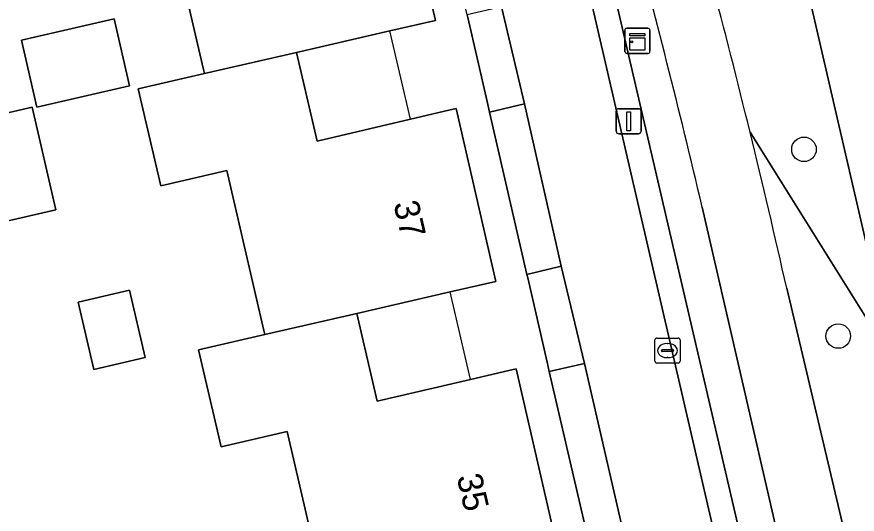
# Model space of a CAD drawing. Extents: x 156412 to 157779, y 382335 to 383768.
# Drawn here: x 156939.8 to 156973.27, y 382923.76 to 382943.57 of the extents above; entities that cross this region are included whole.
import ezdxf

# ---------------------------------------------------------------- set-up
doc = ezdxf.new("R2010")
doc.units = 0
for name, color, linetype in [('IMGEO_Berm_groen', 7, 'Continuous'), ('IMGEO_Boom', 7, 'Continuous'), ('IMGEO_Erf', 7, 'Continuous'), ('IMGEO_Fietspad_gesloten', 7, 'Continuous'), ('IMGEO_Groenvoorziening', 7, 'Continuous'), ('IMGEO_Haag', 7, 'Continuous'), ('IMGEO_Kast', 7, 'Continuous'), ('IMGEO_Kolk', 7, 'Continuous'), ('IMGEO_Lichtmast', 7, 'Continuous'), ('IMGEO_Pand', 7, 'Continuous'), ('IMGEO_Pand_nummerreeks', 7, 'Continuous'), ('IMGEO_Pand_overbouw', 7, 'Continuous'), ('IMGEO_Rijbaan_lokaal_open', 7, 'Continuous'), ('IMGEO_Rijbaan_regionaal_gesloten', 7, 'Continuous'), ('IMGEO_Voetpad_open', 7, 'Continuous')]:
    doc.layers.add(name, color=color, linetype=linetype)

msp = doc.modelspace()

# ---------------------------------------------------------------- linework, layer by layer
at = {"layer": 'IMGEO_Berm_groen'}
for points in [[(156969, 382938.98), (156974.712, 382929.839), (156971.043, 382945.704)], [(156980.671, 382903.778), (156977.118, 382919.414), (156974.712, 382929.839), (156969, 382938.98)], [(156970.46, 382932.76), (156978.859, 382897.233)]]:
    msp.add_lwpolyline(points, dxfattribs=at)
for points in [[(156960.013, 382940.109), (156958.628, 382939.774), (156960.116, 382933.313), (156961.48, 382933.643)], [(156962.404, 382929.759), (156961.007, 382929.446), (156962.495, 382922.988), (156963.893, 382923.301)]]:
    msp.add_lwpolyline(points, close=True, dxfattribs=at)
for centre, radius, start, end in [((156640.671, 382858.578), 338.03, 13.75987, 15.89102), ((156644.824, 382859.606), 333.752, 12.66129, 13.75813)]:
    msp.add_arc(centre, radius, start, end, dxfattribs=at)
at = {"layer": 'IMGEO_Boom'}
for centre in [(156971.148, 382938.294), (156972.514, 382930.857)]:
    msp.add_circle(centre, 0.489, dxfattribs=at)
at = {"layer": 'IMGEO_Erf'}
for points in [[(156943.885, 382953.85), (156941.48, 382953.262), (156933.668, 382951.485), (156923.153, 382949.089), (156923.606, 382947.103), (156935.097, 382949.756), (156936.197, 382944.981), (156936.242, 382944.786), (156932.327, 382943.884), (156933.568, 382938.516), (156933.595, 382938.399), (156940.416, 382939.971), (156941.36, 382935.888), (156934.538, 382934.316), (156935.969, 382928.126), (156938.368, 382917.746)], [(156955.398, 382948.066), (156956.474, 382943.428), (156954.652, 382943.009), (156950.939, 382942.155), (156951.763, 382938.625), (156955.473, 382939.492), (156957.002, 382939.85), (156957.294, 382939.918), (156958.877, 382933.032), (156957.056, 382932.613), (156953.343, 382931.76), (156954.156, 382928.261), (156957.867, 382929.123), (156959.396, 382929.479), (156959.688, 382929.547), (156961.304, 382922.502)], [(156952.114, 382920.354), (156950.566, 382927.05), (156947.935, 382926.443), (156947.041, 382930.311), (156949.673, 382930.916), (156949.634, 382931.083), (156949.303, 382932.514), (156948.164, 382937.446), (156945.533, 382936.839), (156944.639, 382940.707), (156947.27, 382941.312), (156947.231, 382941.479), (156946.995, 382942.502), (156945.95, 382947.023)], [(156962.495, 382922.988), (156961.007, 382929.446), (156960.923, 382929.812), (156960.147, 382933.18), (156960.116, 382933.313), (156958.628, 382939.774), (156958.531, 382940.198), (156957.757, 382943.551), (156957.734, 382943.651), (156957.201, 382945.894)]]:
    msp.add_lwpolyline(points, dxfattribs=at)
for points in [[(156939.981, 382942.644), (156943.671, 382943.497), (156944.288, 382940.825), (156940.598, 382939.972)], [(156942.24, 382932.206), (156944.293, 382932.681), (156944.913, 382929.996), (156942.861, 382929.522)]]:
    msp.add_lwpolyline(points, close=True, dxfattribs=at)
at = {"layer": 'IMGEO_Fietspad_gesloten'}
for points in [[(156967.094, 382935.993), (156971.591, 382916.445), (156974.262, 382905.075), (156976.72, 382895.4)], [(156978.859, 382897.233), (156970.46, 382932.76)]]:
    msp.add_lwpolyline(points, dxfattribs=at)
for centre, radius, start, end in [((156640.671, 382858.578), 338.03, 13.75987, 15.89102), ((156682.4, 382869.623), 292.328, 13.12282, 15.44279), ((156644.824, 382859.606), 333.752, 12.66129, 13.75813)]:
    msp.add_arc(centre, radius, start, end, dxfattribs=at)
at = {"layer": 'IMGEO_Groenvoorziening'}
msp.add_lwpolyline([(156962.016, 382947.078), (156969.739, 382913.653), (156970.724, 382913.858), (156963.505, 382944.87)], dxfattribs=at)
at = {"layer": 'IMGEO_Haag'}
msp.add_lwpolyline([(156962.016, 382947.078), (156969.739, 382913.653), (156970.724, 382913.858), (156963.505, 382944.87)], dxfattribs=at)
at = {"layer": 'IMGEO_Kast'}
for p, q in [((156964.013, 382942.192), (156964.013, 382943.033)), ((156964.013, 382943.033), (156964.013, 382942.192)), ((156964.088, 382943.117), (156964.929, 382943.117)), ((156964.929, 382943.117), (156964.088, 382943.117)), ((156965.013, 382943.042), (156965.013, 382942.201)), ((156965.013, 382942.201), (156965.013, 382943.042)), ((156964.938, 382942.117), (156964.097, 382942.117)), ((156964.097, 382942.117), (156964.938, 382942.117))]:
    msp.add_line(p, q, dxfattribs=at)
for points in [[(156964.208, 382942.907), (156964.808, 382942.907), (156964.808, 382942.822), (156964.208, 382942.822), (156964.208, 382942.907)], [(156964.208, 382942.732), (156964.808, 382942.732), (156964.808, 382942.243), (156964.208, 382942.243), (156964.208, 382942.732)]]:
    msp.add_lwpolyline(points, dxfattribs=at)
msp.add_circle((156964.292, 382942.581), 0.0377, dxfattribs=at)
for centre, start, end in [((156964.091, 382943.039), 92.4484, 184.2845), ((156964.091, 382943.039), 92.4484, 184.2845), ((156964.935, 382943.039), 2.4484, 94.2845), ((156964.935, 382943.039), 2.4484, 94.2845), ((156964.091, 382942.195), 182.4484, 274.2845), ((156964.091, 382942.195), 182.4484, 274.2845), ((156964.935, 382942.195), 272.4484, 4.2845), ((156964.935, 382942.195), 272.4484, 4.2845)]:
    msp.add_arc(centre, 0.0779, start, end, dxfattribs=at)
at = {"layer": 'IMGEO_Kolk'}
for p, q in [((156965.212, 382929.852), (156965.212, 382930.704)), ((156965.287, 382930.778), (156966.139, 382930.778)), ((156965.7, 382930.558), (156965.725, 382930.558)), ((156966.213, 382930.704), (156966.213, 382929.852)), ((156965.471, 382930.272), (156965.471, 382930.284)), ((156965.909, 382930.235), (156965.511, 382930.235)), ((156965.514, 382930.321), (156965.912, 382930.321)), ((156965.955, 382930.284), (156965.955, 382930.272)), ((156965.723, 382929.998), (156965.698, 382929.998)), ((156966.139, 382929.778), (156965.287, 382929.778))]:
    msp.add_line(p, q, dxfattribs=at)
for points in [[(156965.212, 382929.852), (156965.212, 382930.704)], [(156965.287, 382930.778), (156966.139, 382930.778)], [(156966.213, 382930.704), (156966.213, 382929.852)], [(156966.139, 382929.778), (156965.287, 382929.778)]]:
    msp.add_lwpolyline(points, dxfattribs=at)
for centre, radius, start, end in [((156965.289, 382930.702), 0.0765, 91.552, 178.448), ((156965.289, 382930.702), 0.0765, 91.552, 178.448), ((156966.137, 382930.702), 0.0765, 1.552, 88.448), ((156966.137, 382930.702), 0.0765, 1.552, 88.448), ((156965.511, 382930.281), 0.0403, 85.8775, 175.7526), ((156965.508, 382930.271), 0.0366, 178.938, 274.7102), ((156965.912, 382930.278), 0.043, 264.8664, 352.4533), ((156965.916, 382930.283), 0.0386, 1.7309, 96.639), ((156965.289, 382929.854), 0.0765, 181.552, 268.448), ((156965.289, 382929.854), 0.0765, 181.552, 268.448), ((156966.137, 382929.854), 0.0765, 271.552, 358.448), ((156966.137, 382929.854), 0.0765, 271.552, 358.448)]:
    msp.add_arc(centre, radius, start, end, dxfattribs=at)
for centre, major_axis, ratio, start_param, end_param in [((156965.699, 382930.278), (-0.387, 0.002), 0.722429, 4.712389, 7.853982), ((156965.724, 382930.278), (-0.39, 0.002), 0.717154, 1.570796, 4.712389)]:
    msp.add_ellipse(centre, major_axis=major_axis, ratio=ratio, start_param=start_param, end_param=end_param, dxfattribs=at)
at = {"layer": 'IMGEO_Lichtmast'}
for p, q in [((156963.769, 382939.913), (156964.559, 382939.913)), ((156964.559, 382939.913), (156963.769, 382939.913)), ((156963.669, 382939.013), (156963.669, 382939.813)), ((156963.669, 382939.813), (156963.669, 382939.013)), ((156964.659, 382939.813), (156964.659, 382939.013)), ((156964.659, 382939.013), (156964.659, 382939.813)), ((156964.559, 382938.913), (156963.769, 382938.913)), ((156963.769, 382938.913), (156964.559, 382938.913))]:
    msp.add_line(p, q, dxfattribs=at)
msp.add_lwpolyline([(156964.089, 382939.788), (156964.239, 382939.788), (156964.239, 382939.038), (156964.089, 382939.038), (156964.089, 382939.788)], dxfattribs=at)
for centre, start, end in [((156963.769, 382939.813), 90, 180), ((156963.769, 382939.813), 90, 180), ((156964.559, 382939.813), 0, 90), ((156964.559, 382939.813), 360, 90), ((156963.769, 382939.013), 180, 270), ((156963.769, 382939.013), 180, 270), ((156964.559, 382939.013), 270, 0), ((156964.559, 382939.013), 270, 0)]:
    msp.add_arc(centre, 0.1, start, end, dxfattribs=at)
at = {"layer": 'IMGEO_Pand'}
for points in [[(156955.398, 382948.066), (156952.389, 382947.377), (156951.381, 382951.731), (156948.396, 382951.045), (156948.004, 382952.731), (156940.936, 382951.102), (156942.037, 382946.327), (156942.082, 382946.132), (156945.95, 382947.023), (156946.995, 382942.502), (156947.231, 382941.479), (156947.27, 382941.312), (156950.939, 382942.155), (156954.652, 382943.009), (156956.474, 382943.428)], [(156939.981, 382942.644), (156940.598, 382939.972), (156944.288, 382940.825), (156943.671, 382943.497)], [(156957.294, 382939.918), (156957.002, 382939.85), (156955.473, 382939.492), (156951.763, 382938.625), (156950.939, 382942.155), (156947.27, 382941.312), (156944.639, 382940.707), (156945.533, 382936.839), (156948.164, 382937.446), (156949.303, 382932.514), (156949.634, 382931.083), (156949.673, 382930.916), (156953.343, 382931.76), (156957.056, 382932.613), (156958.877, 382933.032)], [(156929.849, 382926.712), (156935.969, 382928.126), (156934.538, 382934.316), (156941.36, 382935.888), (156940.416, 382939.971), (156933.595, 382938.399), (156933.568, 382938.516), (156927.468, 382937.075), (156926.003, 382936.749), (156926.795, 382933.256), (156928.237, 382933.576), (156928.545, 382932.269)], [(156942.24, 382932.206), (156942.861, 382929.522), (156944.913, 382929.996), (156944.293, 382932.681)], [(156959.688, 382929.547), (156959.396, 382929.479), (156957.867, 382929.123), (156954.156, 382928.261), (156953.343, 382931.76), (156949.673, 382930.916), (156947.041, 382930.311), (156947.935, 382926.443), (156950.566, 382927.05), (156952.114, 382920.354), (156955.775, 382921.2), (156959.483, 382922.073), (156961.012, 382922.433), (156961.304, 382922.502)]]:
    msp.add_lwpolyline(points, close=True, dxfattribs=at)
at = {"layer": 'IMGEO_Pand_overbouw'}
for points in [[(156950.939, 382942.155), (156951.763, 382938.625), (156955.473, 382939.492), (156954.652, 382943.009)], [(156957.056, 382932.613), (156953.343, 382931.76), (156954.156, 382928.261), (156957.867, 382929.123)]]:
    msp.add_lwpolyline(points, close=True, dxfattribs=at)
at = {"layer": 'IMGEO_Rijbaan_lokaal_open'}
for points in [[(156970.186, 382911.656), (156969.739, 382913.653), (156962.016, 382947.078)], [(156958.566, 382946.144), (156959.106, 382943.965), (156960.013, 382940.109), (156961.48, 382933.643), (156962.404, 382929.759), (156963.893, 382923.301), (156964.788, 382919.419), (156966.304, 382912.922), (156967.191, 382909.029), (156968.672, 382902.622), (156969.571, 382898.721), (156971.049, 382892.253), (156971.963, 382888.316), (156973.458, 382881.906), (156974.345, 382878.02), (156975.921, 382871.265), (156979.349, 382872.063), (156970.186, 382911.656)]]:
    msp.add_lwpolyline(points, dxfattribs=at)
for points in [[(156959.106, 382943.965), (156957.734, 382943.651), (156957.757, 382943.551), (156958.531, 382940.198), (156958.628, 382939.774), (156960.013, 382940.109)], [(156961.48, 382933.643), (156960.116, 382933.313), (156960.147, 382933.18), (156960.923, 382929.812), (156961.007, 382929.446), (156962.404, 382929.759)]]:
    msp.add_lwpolyline(points, close=True, dxfattribs=at)
at = {"layer": 'IMGEO_Rijbaan_regionaal_gesloten'}
msp.add_lwpolyline([(156971.043, 382945.704), (156974.712, 382929.839), (156977.118, 382919.414), (156980.671, 382903.778)], dxfattribs=at)
at = {"layer": 'IMGEO_Voetpad_open'}
for points in [[(156963.505, 382944.87), (156970.724, 382913.858), (156969.739, 382913.653), (156970.186, 382911.656), (156971.181, 382911.897), (156977.681, 382883.591)], [(156976.72, 382895.4), (156974.262, 382905.075), (156971.591, 382916.445), (156967.094, 382935.993)]]:
    msp.add_lwpolyline(points, dxfattribs=at)
msp.add_arc((156682.4, 382869.623), 292.328, 13.12282, 15.44279, dxfattribs=at)

# ---------------------------------------------------------------- texts
at = {"layer": 'IMGEO_Pand_nummerreeks'}
for s, p in [('37', (156954.795, 382936.136)), ('35', (156957.313, 382925.256))]:
    msp.add_text(s, height=1, rotation=283.0002, dxfattribs=at).set_placement(p)

doc.saveas('drawing.dxf')
